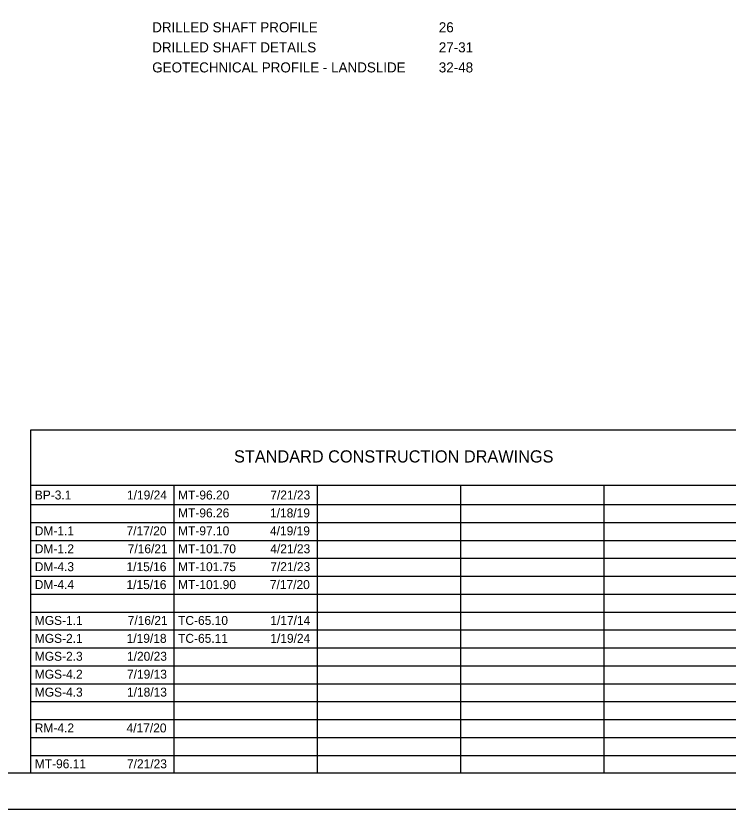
# Model space of a CAD drawing. Extents: x 0 to 34, y 0 to 22.
# Drawn here: x 9.94 to 19.88, y 0 to 11.07 of the extents above; entities that cross this region are included whole.
import ezdxf

# ---------------------------------------------------------------- set-up
doc = ezdxf.new("R2010")
doc.units = 0
for name, color, linetype in [('SH_Border', 7, 'Continuous'), ('SH_Cut_Line', 7, 'Continuous'), ('SH_Data', 7, 'Continuous'), ('SH_Text', 7, 'Continuous')]:
    doc.layers.add(name, color=color, linetype=linetype)

msp = doc.modelspace()

# ---------------------------------------------------------------- linework, layer by layer
at = {"layer": 'SH_Border'}
msp.add_lwpolyline([(1.5, 21.5), (33.5, 21.5), (33.5, 0.5), (1.5, 0.5)], close=True, dxfattribs=at)
at = {"layer": 'SH_Cut_Line'}
msp.add_lwpolyline([(0, 0), (34, 0), (34, 22), (0, 22)], close=True, dxfattribs=at)
at = {"layer": 'SH_Data'}
for p, q in [((10.15, 5.292), (23.6, 5.292)), ((10.15, 0.5), (10.15, 5.292)), ((10.15, 4.521), (23.6, 4.521)), ((12.15, 0.5), (12.15, 4.521)), ((14.15, 0.5), (14.15, 4.521)), ((16.15, 0.5), (16.15, 4.521)), ((18.15, 0.5), (18.15, 4.521)), ((10.15, 4.25), (23.6, 4.25)), ((10.15, 4), (23.6, 4)), ((10.15, 3.75), (23.6, 3.75)), ((10.15, 3.5), (23.6, 3.5)), ((10.15, 3.25), (23.6, 3.25)), ((10.15, 3), (23.6, 3)), ((10.15, 2.75), (23.6, 2.75)), ((10.15, 2.5), (23.6, 2.5)), ((10.15, 2.25), (23.6, 2.25)), ((10.15, 2), (23.6, 2)), ((10.15, 1.75), (23.6, 1.75)), ((10.15, 1.5), (23.6, 1.5)), ((10.15, 1.25), (23.6, 1.25)), ((10.15, 1), (23.6, 1)), ((10.15, 0.75), (23.6, 0.75))]:
    msp.add_line(p, q, dxfattribs=at)

# ---------------------------------------------------------------- texts
at = {"layer": 'SH_Text'}
for s, height, p in [('DRILLED SHAFT PROFILE', 0.14, (11.844, 10.838)), ('26', 0.14, (15.844, 10.838)), ('DRILLED SHAFT DETAILS', 0.14, (11.844, 10.558)), ('27-31', 0.14, (15.844, 10.558)), ('GEOTECHNICAL PROFILE - LANDSLIDE', 0.14, (11.844, 10.278)), ('32-48', 0.14, (15.844, 10.278)), ('STANDARD CONSTRUCTION DRAWINGS', 0.17, (12.986, 4.836)), ('BP-3.1', 0.125, (10.205, 4.32)), ('1/19/24', 0.125, (11.492, 4.32)), ('MT-96.20', 0.125, (12.205, 4.32)), ('7/21/23', 0.125, (13.492, 4.32)), ('MT-96.26', 0.125, (12.205, 4.07)), ('1/18/19', 0.125, (13.488, 4.07)), ('DM-1.1', 0.125, (10.205, 3.82)), ('7/17/20', 0.125, (11.486, 3.82)), ('MT-97.10', 0.125, (12.205, 3.82)), ('4/19/19', 0.125, (13.488, 3.82)), ('DM-1.2', 0.125, (10.205, 3.57)), ('7/16/21', 0.125, (11.502, 3.57)), ('MT-101.70', 0.125, (12.205, 3.57)), ('4/21/23', 0.125, (13.492, 3.57)), ('DM-4.3', 0.125, (10.205, 3.32)), ('1/15/16', 0.125, (11.485, 3.32)), ('MT-101.75', 0.125, (12.205, 3.32)), ('7/21/23', 0.125, (13.492, 3.32)), ('DM-4.4', 0.125, (10.205, 3.07)), ('1/15/16', 0.125, (11.485, 3.07)), ('MT-101.90', 0.125, (12.205, 3.07)), ('7/17/20', 0.125, (13.486, 3.07)), ('MGS-1.1', 0.125, (10.205, 2.57)), ('7/16/21', 0.125, (11.502, 2.57)), ('TC-65.10', 0.125, (12.205, 2.57)), ('1/17/14', 0.125, (13.492, 2.57)), ('MGS-2.1', 0.125, (10.205, 2.32)), ('1/19/18', 0.125, (11.487, 2.32)), ('TC-65.11', 0.125, (12.205, 2.32)), ('1/19/24', 0.125, (13.492, 2.32)), ('MGS-2.3', 0.125, (10.205, 2.07)), ('1/20/23', 0.125, (11.492, 2.07)), ('MGS-4.2', 0.125, (10.205, 1.82)), ('7/19/13', 0.125, (11.492, 1.82)), ('MGS-4.3', 0.125, (10.205, 1.57)), ('1/18/13', 0.125, (11.492, 1.57)), ('RM-4.2', 0.125, (10.205, 1.07)), ('4/17/20', 0.125, (11.486, 1.07)), ('MT-96.11', 0.125, (10.205, 0.57)), ('7/21/23', 0.125, (11.492, 0.57))]:
    msp.add_text(s, height=height, dxfattribs=at).set_placement(p)

doc.saveas('drawing.dxf')
